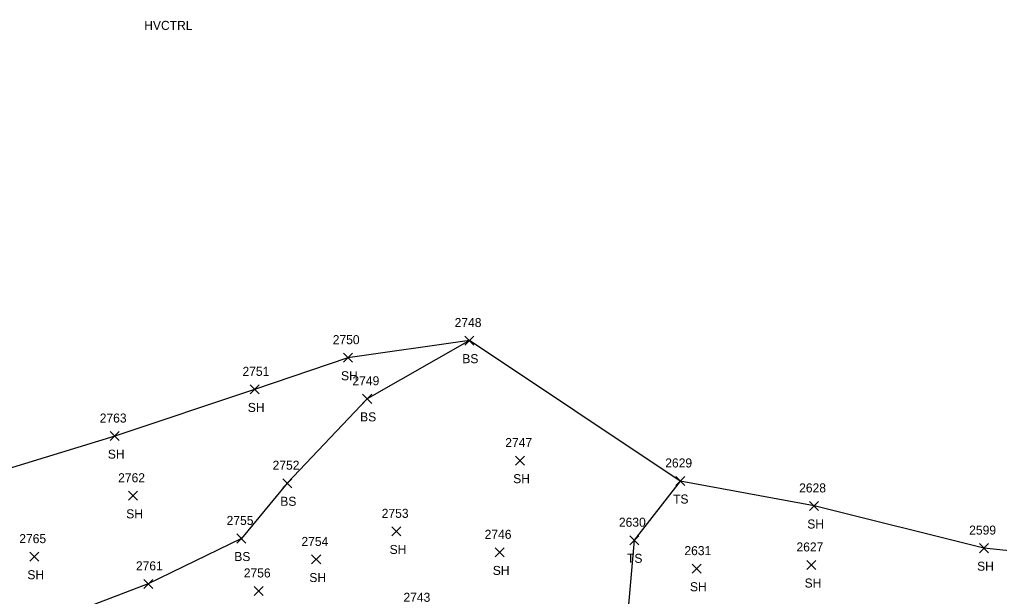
# Model space of a CAD drawing. Extents: x 1443590 to 1445966, y 578314 to 580556.
# Drawn here: x 1444550.7 to 1444767.8, y 579207.6 to 579335.5 of the extents above; entities that cross this region are included whole.
import ezdxf

# ---------------------------------------------------------------- set-up
doc = ezdxf.new("R2010")
doc.units = 0
for name, color, linetype in [('C_A', 7, 'Continuous'), ('L_A', 7, 'Continuous'), ('L_I', 7, 'Continuous'), ('L_TIC', 7, 'Continuous'), ('LELB', 7, 'Continuous'), ('LSOGP', 7, 'Continuous')]:
    doc.layers.add(name, color=color, linetype=linetype)

msp = doc.modelspace()

# ---------------------------------------------------------------- linework, layer by layer
at = {"layer": 'L_TIC'}
for points in [[(1444649.34, 579263.33), (1444651.34, 579265.33)], [(1444651.34, 579263.33), (1444649.34, 579265.33)], [(1444622.42, 579259.54), (1444624.42, 579261.54)], [(1444624.42, 579259.54), (1444622.42, 579261.54)], [(1444601.76, 579252.52), (1444603.76, 579254.52)], [(1444603.76, 579252.52), (1444601.76, 579254.52)], [(1444626.7, 579250.43), (1444628.7, 579252.43)], [(1444628.7, 579250.43), (1444626.7, 579252.43)], [(1444570.75, 579242.17), (1444572.75, 579244.17)], [(1444572.75, 579242.17), (1444570.75, 579244.17)], [(1444660.56, 579236.74), (1444662.56, 579238.74)], [(1444662.56, 579236.74), (1444660.56, 579238.74)], [(1444609.01, 579231.72), (1444611.01, 579233.72)], [(1444611.01, 579231.72), (1444609.01, 579233.72)], [(1444696.07, 579232.22), (1444698.07, 579234.22)], [(1444698.07, 579232.22), (1444696.07, 579234.22)], [(1444574.82, 579228.94), (1444576.82, 579230.94)], [(1444576.82, 579228.94), (1444574.82, 579230.94)], [(1444725.72, 579226.69), (1444727.72, 579228.69)], [(1444727.72, 579226.69), (1444725.72, 579228.69)], [(1444633.18, 579221.05), (1444635.18, 579223.05)], [(1444635.18, 579221.05), (1444633.18, 579223.05)], [(1444598.82, 579219.48), (1444600.82, 579221.48)], [(1444600.82, 579219.48), (1444598.82, 579221.48)], [(1444685.87, 579219.09), (1444687.87, 579221.09)], [(1444687.87, 579219.09), (1444685.87, 579221.09)], [(1444656.05, 579216.4), (1444658.05, 579218.4)], [(1444658.05, 579216.4), (1444656.05, 579218.4)], [(1444763.36, 579217.34), (1444765.36, 579219.34)], [(1444765.36, 579217.34), (1444763.36, 579219.34)], [(1444552.92, 579215.45), (1444554.92, 579217.45)], [(1444554.92, 579215.45), (1444552.92, 579217.45)], [(1444615.4, 579214.83), (1444617.4, 579216.83)], [(1444617.4, 579214.83), (1444615.4, 579216.83)], [(1444725.13, 579213.61), (1444727.13, 579215.61)], [(1444727.13, 579213.61), (1444725.13, 579215.61)], [(1444699.73, 579212.79), (1444701.73, 579214.79)], [(1444701.73, 579212.79), (1444699.73, 579214.79)], [(1444578.2, 579209.42), (1444580.2, 579211.42)], [(1444580.2, 579209.42), (1444578.2, 579211.42)], [(1444602.68, 579207.85), (1444604.68, 579209.85)], [(1444604.68, 579207.85), (1444602.68, 579209.85)]]:
    msp.add_lwpolyline(points, dxfattribs=at)
at = {"layer": 'LELB'}
for points in [[(1444650.34, 579264.33), (1444627.7, 579251.43), (1444610.01, 579232.72), (1444599.82, 579220.48), (1444579.2, 579210.42), (1444554.69, 579201.02), (1444532.48, 579211.13), (1444505.21, 579222.61)], [(1444697.07, 579233.22), (1444686.87, 579220.09), (1444685.3, 579202.42), (1444695.59, 579190.16)]]:
    msp.add_lwpolyline(points, dxfattribs=at)
at = {"layer": 'LSOGP'}
msp.add_lwpolyline([(1444847.54, 579350.44), (1444854.99, 579326.23), (1444879.7, 579311.33), (1444890.2, 579279.95), (1444904.73, 579247.14), (1444888.76, 579222.89), (1444863.33, 579217), (1444835.47, 579215.08), (1444803.04, 579214.28), (1444764.36, 579218.34), (1444726.72, 579227.69), (1444697.07, 579233.22), (1444650.35, 579264.33), (1444623.43, 579260.54), (1444602.77, 579253.51), (1444571.76, 579243.16), (1444548.12, 579235.92)], dxfattribs=at)

# ---------------------------------------------------------------- texts
at = {"layer": 'C_A'}
msp.add_text('HVCTRL', height=2, dxfattribs=at).set_placement((1444578.3, 579333.18))
at = {"layer": 'L_A'}
for s, p in [('BS', (1444648.78, 579259.33)), ('SH', (1444621.91, 579255.54)), ('SH', (1444601.25, 579248.52)), ('BS', (1444626.14, 579246.43)), ('SH', (1444570.24, 579238.17)), ('SH', (1444660.05, 579232.74)), ('BS', (1444608.45, 579227.72)), ('TS', (1444695.48, 579228.22)), ('SH', (1444574.31, 579224.94)), ('SH', (1444725.21, 579222.69)), ('BS', (1444598.26, 579215.48)), ('SH', (1444632.67, 579217.05)), ('TS', (1444685.28, 579215.09)), ('SH', (1444762.84, 579213.34)), ('SH', (1444552.41, 579211.45)), ('SH', (1444655.53, 579212.4)), ('SH', (1444614.89, 579210.83)), ('SH', (1444724.62, 579209.61)), ('SH', (1444699.22, 579208.79))]:
    msp.add_text(s, height=2, dxfattribs=at).set_placement(p)
at = {"layer": 'L_I'}
for s, p in [('2748', (1444647.08, 579267.33)), ('2750', (1444620.07, 579263.54)), ('2751', (1444600.07, 579256.52)), ('2749', (1444624.44, 579254.43)), ('2763', (1444568.44, 579246.17)), ('2747', (1444658.3, 579240.74)), ('2752', (1444606.75, 579235.72)), ('2629', (1444693.75, 579236.22)), ('2762', (1444572.52, 579232.94)), ('2628', (1444723.41, 579230.69)), ('2753', (1444630.92, 579225.05)), ('2755', (1444596.56, 579223.48)), ('2630', (1444683.48, 579223.09)), ('2746', (1444653.73, 579220.4)), ('2599', (1444761.09, 579221.34)), ('2765', (1444550.62, 579219.45)), ('2754', (1444613.14, 579218.83)), ('2631', (1444697.99, 579216.79)), ('2627', (1444722.82, 579217.61)), ('2761', (1444576.46, 579213.42)), ('2756', (1444600.36, 579211.85)), ('2743', (1444635.74, 579206.45))]:
    msp.add_text(s, height=2, dxfattribs=at).set_placement(p)

doc.saveas('drawing.dxf')
